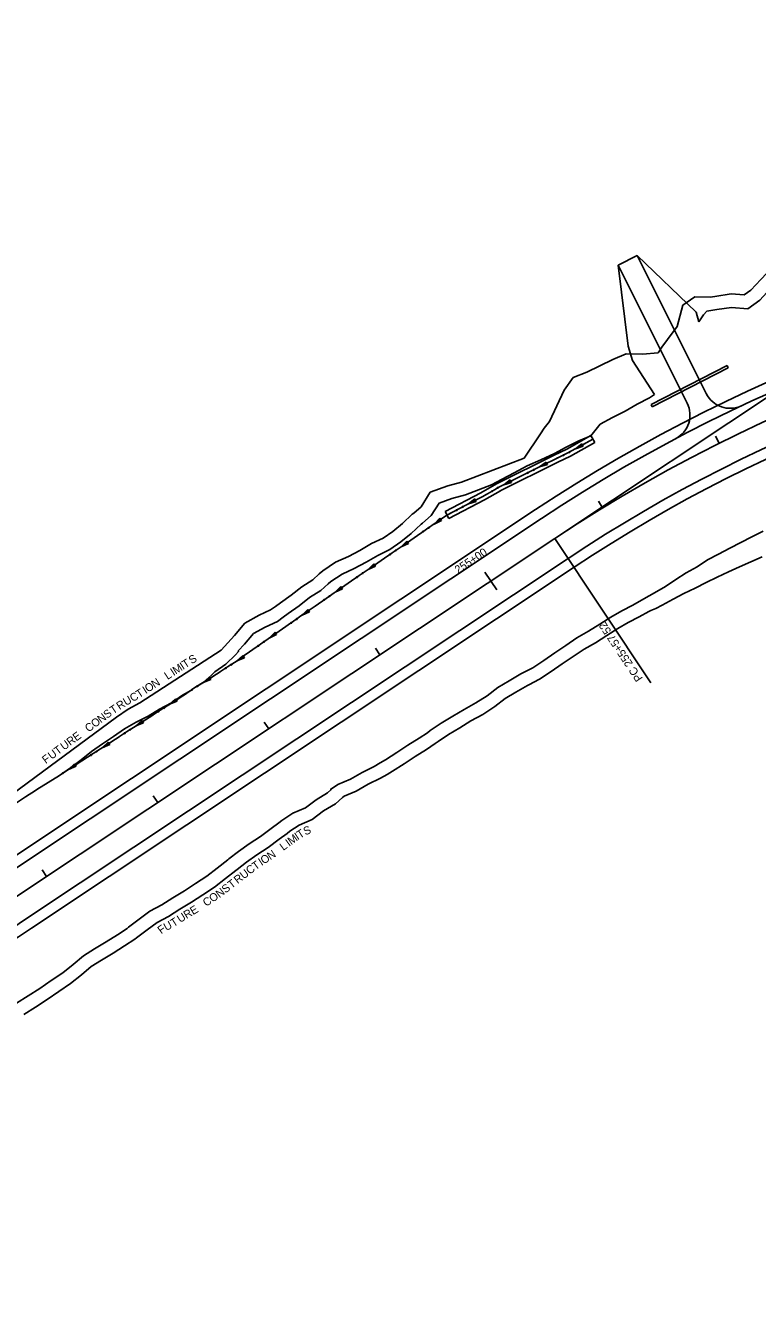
# Model space of a CAD drawing. Extents: x 979959 to 994833, y 1835619 to 1845316.
# Drawn here: x 990716 to 991264, y 1838866 to 1839827 of the extents above; entities that cross this region are included whole.
import ezdxf

# ---------------------------------------------------------------- set-up
doc = ezdxf.new("R2010")
doc.units = 0
for name, color, linetype in [('Future 5 Lane Construction Limits', 7, 'Continuous'), ('R_CONCRETE', 7, 'Continuous'), ('R_Drainage', 7, 'Continuous'), ('R_Horz Alg', 7, 'Continuous'), ('R_Horz Alg Annot', 7, 'Continuous'), ('R_Horz Alg Annot_Side Road', 7, 'Continuous'), ('R_Horz Alg Stationing', 7, 'Continuous'), ('R_Proposed Const Limits', 7, 'Continuous'), ('R_Proposed Road', 7, 'Continuous'), ('R_Special Ditch', 7, 'Continuous')]:
    doc.layers.add(name, color=color, linetype=linetype)

msp = doc.modelspace()

# ---------------------------------------------------------------- linework, layer by layer
at = {"layer": 'Future 5 Lane Construction Limits'}
for points in [[(991229, 1839623.66), (991232.48, 1839624.14), (991244.6, 1839626.05), (991254.36, 1839625.25), (991259.48, 1839628.86), (991266.81, 1839636.85), (991275.9, 1839646.46), (991287.91, 1839653.93), (991299.82, 1839656.21), (991312.97, 1839660.84), (991329.68, 1839653.8), (991340.76, 1839650.38), (991348.81, 1839650.03), (991356.19, 1839652.94), (991366.08, 1839658.22), (991377.97, 1839661.82), (991394.1, 1839664.03), (991403.52, 1839655.37)], [(991089.5, 1839502.75), (991101.68, 1839521.18), (991104.45, 1839525.27), (991108.57, 1839530.28), (991113.93, 1839542.04), (991119.42, 1839553.86), (991126.34, 1839563.44), (991136.53, 1839567.44), (991146.32, 1839572.09), (991156.04, 1839576.84), (991166.01, 1839581.11), (991178.33, 1839580.84), (991189.85, 1839581.92), (991192.79, 1839586.18), (991196.85, 1839591.87), (991204.12, 1839601.5), (991208.41, 1839617.6), (991217.51, 1839623.91), (991229, 1839623.66)], [(990862.34, 1839358.81), (990872.37, 1839370), (990880.21, 1839379.25), (990890.96, 1839385.09), (990899.52, 1839389.07), (990903.06, 1839391.67), (990906.89, 1839394.43), (990914.87, 1839400.13), (990922.99, 1839406.49), (990931.11, 1839411.62), (990935.94, 1839416.07), (990938.54, 1839418.42), (990948.16, 1839424.76), (990957.87, 1839429.23), (990966.35, 1839433.52), (990975.03, 1839438.79), (990983.86, 1839442.94), (990991.01, 1839447.99), (990998.27, 1839453.99), (991005.73, 1839460.82), (991006.85, 1839461.75), (991012.24, 1839466.48), (991019.18, 1839477.31), (991032.39, 1839482.21), (991042.56, 1839484.92), (991089.5, 1839502.75)], [(991183.02, 1839388), (991184.55, 1839388.69), (991188.27, 1839390.16), (991193.03, 1839392.59), (991201.12, 1839397.08), (991209.33, 1839401.37), (991217.71, 1839405.35), (991225.94, 1839409.57), (991234.2, 1839413.72), (991242.58, 1839417.62), (991251.02, 1839421.41), (991259.45, 1839425.17), (991267.89, 1839428.92)], [(990714.51, 1839085.77), (990723.26, 1839091.18), (990732.12, 1839096.93), (990740.78, 1839102.81), (990749.63, 1839108.85), (990757.9, 1839115.47), (990765.1, 1839121.65), (990772.88, 1839126.5), (990781.45, 1839131.66), (990790.11, 1839137.06), (990797.76, 1839142.07), (990799.03, 1839143.03), (990807.07, 1839149.05), (990814.46, 1839154.66), (990822.94, 1839159.23), (990831.56, 1839164.72), (990840.22, 1839169.9), (990848.76, 1839175.52), (990857.41, 1839181.24), (990865.66, 1839187.58), (990873.57, 1839193.74), (990874.38, 1839194.36), (990881.36, 1839199.78), (990889.18, 1839205.38), (990897.6, 1839210.93), (990905.82, 1839217.04), (990911.86, 1839221.42), (990913.83, 1839223.05), (990921.02, 1839227.72), (990930.7, 1839231.89), (990939.22, 1839238.36), (990948.19, 1839243.75), (990953.36, 1839248.47), (990954.76, 1839249.44), (990963.71, 1839253.18), (990972.73, 1839258.27), (990981.82, 1839262.81), (990986.76, 1839265.7), (990990.92, 1839268.18), (990999.6, 1839273.68), (991007.83, 1839279.21), (991016.39, 1839284.45), (991022.88, 1839288.85), (991025, 1839290.46), (991032.81, 1839295.75), (991041.21, 1839300.73), (991049.61, 1839305.84), (991058.52, 1839310.73), (991067.63, 1839316.58), (991075.34, 1839322.64), (991083.41, 1839327.32), (991092.08, 1839332.4), (991092.98, 1839332.93), (991101, 1839337.01), (991109.88, 1839342.93), (991118.14, 1839348.63), (991126.35, 1839354.18), (991134.4, 1839359.53), (991142.94, 1839364.5), (991151.61, 1839369.93), (991159.69, 1839375.14), (991167.47, 1839379.52), (991175.82, 1839383.89), (991183.02, 1839388)], [(990694.71, 1839243.01), (990783.93, 1839308.71), (990792.78, 1839314.53), (990801.53, 1839319.5), (990862.34, 1839358.81)]]:
    msp.add_lwpolyline(points, dxfattribs=at)
at = {"layer": 'R_CONCRETE'}
for p, q in [((991139.58, 1839519.81), (991142.5, 1839514.56)), ((991033.09, 1839457.55), (991030.32, 1839462.87))]:
    msp.add_line(p, q, dxfattribs=at)
for points in [[(991068.8, 1839483.64), (991112.07, 1839505.15), (991121.43, 1839509.7), (991139.58, 1839519.81)], [(991071.64, 1839478.35), (991114.71, 1839499.77), (991124.21, 1839504.38), (991142.5, 1839514.56)], [(991030.32, 1839462.87), (991057.01, 1839476.8), (991068.8, 1839483.64)], [(991033.09, 1839457.55), (991059.9, 1839471.54), (991071.81, 1839478.45)]]:
    msp.add_lwpolyline(points, dxfattribs=at)
at = {"layer": 'R_Drainage'}
for p, q in [((991241.59, 1839572.36), (991184.62, 1839543.21)), ((991242.5, 1839570.58), (991185.53, 1839541.43)), ((991241.59, 1839572.36), (991242.5, 1839570.58)), ((991184.62, 1839543.21), (991185.53, 1839541.43))]:
    msp.add_line(p, q, dxfattribs=at)
at = {"layer": 'R_Horz Alg'}
msp.add_line((991112.49, 1839442.65), (990705.95, 1839172.04), dxfattribs=at)
msp.add_arc((991747.45, 1838488.74), 1145.92, 61.24197, 123.64915, dxfattribs=at)
at = {"layer": 'R_Horz Alg Annot'}
msp.add_lwpolyline([(991112.49, 1839442.65), (991184.53, 1839334.43)], dxfattribs=at)
at = {"layer": 'R_Horz Alg Annot_Side Road'}
msp.add_line((991112.49, 1839442.65), (991690.28, 1839827.25), dxfattribs=at)
at = {"layer": 'R_Horz Alg Stationing'}
for points in [[(991233.02, 1839519.4), (991235.7, 1839514.03)], [(991145.15, 1839470.64), (991148.28, 1839465.53)], [(991060.18, 1839417.44), (991069.04, 1839404.12)], [(990978.04, 1839360.36), (990981.37, 1839355.37)], [(990894.8, 1839304.95), (990898.12, 1839299.96)], [(990811.55, 1839249.54), (990814.88, 1839244.55)], [(990728.31, 1839194.13), (990731.63, 1839189.14)]]:
    msp.add_lwpolyline(points, dxfattribs=at)
at = {"layer": 'R_Proposed Const Limits'}
for p, q in [((991120.91, 1839511.12), (991130.47, 1839515.91)), ((991102.07, 1839501.66), (991091.84, 1839497.03)), ((991055.22, 1839479.03), (991065.08, 1839482.76)), ((990850.42, 1839335.52), (990841.88, 1839330.32)), ((990749.47, 1839270.62), (990741.2, 1839265))]:
    msp.add_line(p, q, dxfattribs=at)
for points in [[(991160.04, 1839647.71), (991167.45, 1839586.9), (991170.67, 1839576.16), (991187.29, 1839550.51)], [(991174.35, 1839654.85), (991218.49, 1839612.37), (991220.39, 1839605.2)], [(991220.39, 1839605.2), (991223.85, 1839610.32), (991226.48, 1839613.23), (991233.93, 1839614.25), (991244.98, 1839615.99), (991257.16, 1839614.98), (991266.12, 1839621.31), (991274.12, 1839630.04), (991282.27, 1839638.65), (991291.62, 1839644.46), (991302.44, 1839646.53), (991312.65, 1839650.13), (991326.25, 1839644.39), (991339.04, 1839640.44), (991350.5, 1839639.94), (991360.4, 1839643.85), (991369.92, 1839648.94), (991380.11, 1839652.02), (991390.79, 1839653.49), (991406.04, 1839639.48)], [(991130.47, 1839515.91), (991139.57, 1839519.69), (991146.56, 1839528.47), (991155.81, 1839533.4), (991165.13, 1839538.2), (991174.27, 1839543.31), (991183.57, 1839548.13), (991187.29, 1839550.51)], [(991102.07, 1839501.66), (991112.33, 1839506.49), (991120.91, 1839511.12)], [(991065.08, 1839482.76), (991073.02, 1839487.23), (991082.12, 1839491.79), (991091.84, 1839497.03)], [(990850.42, 1839335.52), (990857.69, 1839342.65), (990865.88, 1839348.4), (990873.17, 1839355.49), (990875.56, 1839357.94), (990875.32, 1839358.31), (990879.9, 1839363.42), (990886.63, 1839371.36), (990895.45, 1839376.16), (990904.63, 1839380.42), (990908.94, 1839383.58), (990912.72, 1839386.3), (990920.86, 1839392.12), (990928.76, 1839398.3), (990937.22, 1839403.65), (990942.68, 1839408.68), (990944.68, 1839410.49), (990953.03, 1839415.99), (990962.22, 1839420.23), (990971.21, 1839424.77), (990979.76, 1839429.97), (990988.91, 1839434.27), (990997.09, 1839440.04), (991004.83, 1839446.44), (991012.3, 1839453.28), (991013.34, 1839454.14), (991019.9, 1839459.9), (991025.79, 1839469.1), (991035.43, 1839472.67), (991045.63, 1839475.39), (991055.22, 1839479.03)], [(990709.1, 1839094.18), (990717.91, 1839099.63), (990726.59, 1839105.26), (990735.16, 1839111.08), (990743.68, 1839116.9), (990751.52, 1839123.17), (990759.17, 1839129.73), (990767.65, 1839135.02), (990776.23, 1839140.19), (990784.72, 1839145.48), (990792.01, 1839150.26), (990793.04, 1839151.03), (990801.05, 1839157.03), (990809.04, 1839163.09), (990817.87, 1839167.86), (990826.31, 1839173.23), (990834.9, 1839178.37), (990843.25, 1839183.87), (990851.6, 1839189.38), (990859.55, 1839195.49), (990867.46, 1839201.65), (990868.28, 1839202.28), (990875.38, 1839207.79), (990883.52, 1839213.62), (990891.87, 1839219.12), (990899.9, 1839225.1), (990905.72, 1839229.33), (990907.9, 1839231.13), (990916.29, 1839236.57), (990925.63, 1839240.59), (990933.61, 1839246.65), (990942.19, 1839251.81), (990944.68, 1839254.09), (990944.46, 1839254.44), (990949.91, 1839258.25), (990959.31, 1839262.18), (990968.04, 1839267.11), (990977.06, 1839271.61), (990981.67, 1839274.31), (990985.68, 1839276.7), (990994.13, 1839282.06), (991002.43, 1839287.63), (991010.97, 1839292.85), (991017.04, 1839296.97), (991019.16, 1839298.59), (991027.45, 1839304.19), (991036.05, 1839309.31), (991044.61, 1839314.5), (991053.4, 1839319.33), (991061.82, 1839324.73), (991069.71, 1839330.94), (991078.38, 1839335.96), (991087.02, 1839341.03), (991088.17, 1839341.71), (991095.95, 1839345.66), (991104.27, 1839351.21), (991112.5, 1839356.88), (991120.78, 1839362.49), (991129.11, 1839368.02), (991137.77, 1839373.06), (991146.25, 1839378.37), (991154.52, 1839383.71), (991162.7, 1839388.31), (991171.03, 1839392.67), (991179.16, 1839397.31), (991187.25, 1839402), (991195.38, 1839406.64), (991203.2, 1839411.76), (991211.04, 1839416.9), (991219.18, 1839421.5), (991227.07, 1839426.57), (991235.31, 1839430.99), (991243.61, 1839435.32), (991251.96, 1839439.54), (991260.23, 1839443.92), (991268.55, 1839448.21)], [(990749.47, 1839270.62), (990757.55, 1839276.53), (990765.34, 1839282.87), (990773.53, 1839288.61), (990781.79, 1839294.25), (990790.11, 1839299.81), (990798.75, 1839304.87), (990799.67, 1839305.35), (990807.72, 1839309.44), (990816.31, 1839314.59), (990825.11, 1839319.41), (990833.38, 1839325.04), (990839.67, 1839328.57)], [(990839.69, 1839328.54), (990841.88, 1839330.32)], [(990541.64, 1839140.81), (990550.41, 1839144.98), (990565.69, 1839158.08), (990584.19, 1839164.05), (990592.48, 1839169.08), (990600.74, 1839174.17), (990608.96, 1839179.31), (990617.31, 1839184.24), (990625.76, 1839189.01), (990634.19, 1839193.82), (990642.59, 1839198.68), (990650.8, 1839203.86), (990658.77, 1839209.4), (990666.82, 1839214.81), (990674.9, 1839220.22), (990683.25, 1839225.73), (990691.16, 1839231.9), (990699.42, 1839237.53), (990707.56, 1839243.35), (990715.85, 1839248.95), (990723.21, 1839253.62), (990724.3, 1839254.3), (990732.75, 1839259.64), (990741.2, 1839265)]]:
    msp.add_lwpolyline(points, dxfattribs=at)
at = {"layer": 'R_Proposed Road'}
for p, q in [((991160.04, 1839647.71), (991174.35, 1839654.85)), ((991098.09, 1839464.29), (990691.55, 1839193.69)), ((991102.52, 1839457.64), (990695.98, 1839187.03)), ((991122.47, 1839427.67), (990715.93, 1839157.06)), ((991126.9, 1839421.01), (990720.36, 1839150.4))]:
    msp.add_line(p, q, dxfattribs=at)
for points in [[(991160.04, 1839647.71), (991211.72, 1839544.16)], [(991174.35, 1839654.85), (991226.03, 1839551.31)]]:
    msp.add_lwpolyline(points, dxfattribs=at)
for centre, radius, start, end in [((991747.45, 1838488.74), 1171.92, 67.29702, 123.64915), ((991747.45, 1838488.74), 1163.92, 67.29702, 123.64915), ((991747.45, 1838488.74), 1127.92, 70.20618, 123.64915), ((991747.45, 1838488.74), 1119.92, 70.20618, 123.64915), ((991243.93, 1839560.24), 20, 206.52507, 295.16988), ((991193.82, 1839535.23), 20, 297.88026, 26.52507), ((989647.69, 1840761.9), 1927.86, 281.66438, 303.64915), ((989647.69, 1840761.9), 1935.86, 281.66438, 303.64915)]:
    msp.add_arc(centre, radius, start, end, dxfattribs=at)
at = {"layer": 'R_Special Ditch'}
for p, q in [((991132.66, 1839513.73), (991127.94, 1839509.89)), ((991127.94, 1839509.89), (991133.69, 1839511.88)), ((991133.69, 1839511.88), (991132.66, 1839513.73)), ((991106.03, 1839499.98), (991101.12, 1839496.36)), ((991101.12, 1839496.36), (991106.97, 1839498.09)), ((991106.97, 1839498.09), (991106.03, 1839499.98)), ((991079.13, 1839486.61), (991074.23, 1839482.99)), ((991074.23, 1839482.99), (991080.07, 1839484.71)), ((991080.07, 1839484.71), (991079.13, 1839486.61)), ((991070.14, 1839480.95), (991067.24, 1839479.02)), ((991070.14, 1839480.95), (991070.14, 1839480.95)), ((991052.69, 1839472.35), (991047.86, 1839468.64)), ((991047.86, 1839468.64), (991053.67, 1839470.48)), ((991053.67, 1839470.48), (991052.69, 1839472.35)), ((991026.32, 1839457.78), (991021.98, 1839453.5)), ((991021.98, 1839453.5), (991027.52, 1839456.04)), ((991027.52, 1839456.04), (991026.32, 1839457.78)), ((991001.59, 1839440.73), (990997.25, 1839436.45)), ((990997.25, 1839436.45), (991002.79, 1839438.99)), ((991002.79, 1839438.99), (991001.59, 1839440.73)), ((990976.86, 1839423.68), (990972.52, 1839419.4)), ((990972.52, 1839419.4), (990978.06, 1839421.93)), ((990978.06, 1839421.93), (990976.86, 1839423.68)), ((990952.13, 1839406.62), (990947.79, 1839402.35)), ((990953.33, 1839404.88), (990952.13, 1839406.62)), ((990947.79, 1839402.35), (990953.33, 1839404.88)), ((990927.47, 1839389.46), (990923.16, 1839385.16)), ((990923.16, 1839385.16), (990928.69, 1839387.72)), ((990928.69, 1839387.72), (990927.47, 1839389.46)), ((990902.84, 1839372.26), (990898.53, 1839367.96)), ((990898.53, 1839367.96), (990904.05, 1839370.53)), ((990904.05, 1839370.53), (990902.84, 1839372.26)), ((990878.75, 1839354.96), (990874.28, 1839350.82)), ((990874.28, 1839350.82), (990879.9, 1839353.18)), ((990879.9, 1839353.18), (990878.75, 1839354.96)), ((990853.5, 1839338.69), (990849.03, 1839334.56)), ((990854.65, 1839336.92), (990853.5, 1839338.69)), ((990849.03, 1839334.56), (990854.65, 1839336.92)), ((990828.27, 1839322.44), (990823.8, 1839318.3)), ((990823.8, 1839318.3), (990829.41, 1839320.66)), ((990829.41, 1839320.66), (990828.27, 1839322.44)), ((990803.02, 1839306.17), (990798.54, 1839302.03)), ((990798.54, 1839302.03), (990804.16, 1839304.39)), ((990804.16, 1839304.39), (990803.02, 1839306.17)), ((990777.78, 1839289.87), (990773.32, 1839285.73)), ((990778.93, 1839288.1), (990777.78, 1839289.87)), ((990773.32, 1839285.73), (990778.93, 1839288.1)), ((990752.55, 1839273.57), (990748.09, 1839269.43)), ((990748.09, 1839269.43), (990753.7, 1839271.8)), ((990753.7, 1839271.8), (990752.55, 1839273.57)), ((990749.61, 1839270.41), (990741.2, 1839265))]:
    msp.add_line(p, q, dxfattribs=at)
for points in [[(991141.04, 1839517.19), (991122.82, 1839507.04), (991113.39, 1839502.46), (991103.99, 1839497.79)], [(991141.04, 1839517.19), (991127.94, 1839509.89)], [(991114.56, 1839503.03), (991113.39, 1839502.46), (991103.99, 1839497.79), (991101.12, 1839496.36)], [(991114.6, 1839503.04), (991114.56, 1839503.03)], [(991103.99, 1839497.79), (991070.14, 1839480.95)], [(991087.66, 1839489.67), (991074.23, 1839482.99)], [(991087.69, 1839489.68), (991087.66, 1839489.67)], [(991067.24, 1839479.02), (991058.46, 1839474.17), (991049.54, 1839469.52), (991040.62, 1839464.86), (991031.71, 1839460.21), (991023.47, 1839454.54), (991016.34, 1839449.62), (991015.24, 1839448.86), (991007.01, 1839443.18), (990998.77, 1839437.5), (990990.54, 1839431.82), (990982.31, 1839426.15), (990974.07, 1839420.47), (990965.84, 1839414.79), (990957.61, 1839409.11), (990949.37, 1839403.43), (990947.18, 1839401.92), (990941.16, 1839397.72), (990932.96, 1839392), (990924.76, 1839386.27), (990916.56, 1839380.55), (990912.74, 1839377.88), (990908.36, 1839374.82), (990900.15, 1839369.1), (990891.95, 1839363.37), (990883.75, 1839357.64), (990878.3, 1839353.84), (990878.49, 1839353.53), (990875.68, 1839351.72), (990867.27, 1839346.31), (990858.86, 1839340.89), (990850.46, 1839335.47), (990841.88, 1839330.32)], [(991061.13, 1839475.64), (991058.46, 1839474.17), (991049.54, 1839469.52), (991047.86, 1839468.64)], [(991061.16, 1839475.66), (991061.13, 1839475.64)], [(991034.53, 1839461.68), (991031.71, 1839460.21), (991023.47, 1839454.54), (991021.98, 1839453.5)], [(991034.56, 1839461.7), (991034.53, 1839461.68)], [(991009.6, 1839444.97), (991007.01, 1839443.18), (990998.77, 1839437.5), (990997.25, 1839436.45)], [(991009.63, 1839444.99), (991009.6, 1839444.97)], [(990984.87, 1839427.91), (990982.31, 1839426.15), (990974.07, 1839420.47), (990972.52, 1839419.4)], [(990984.9, 1839427.94), (990984.87, 1839427.91)], [(990960.14, 1839410.86), (990957.61, 1839409.11), (990949.37, 1839403.43), (990947.79, 1839402.35)], [(990960.17, 1839410.88), (990960.14, 1839410.86)], [(990935.46, 1839393.74), (990932.96, 1839392), (990924.76, 1839386.27), (990923.16, 1839385.16)], [(990935.49, 1839393.76), (990935.46, 1839393.74)], [(990910.83, 1839376.55), (990908.36, 1839374.82), (990900.15, 1839369.1), (990898.53, 1839367.96)], [(990910.86, 1839376.57), (990910.83, 1839376.55)], [(990886.2, 1839359.35), (990883.75, 1839357.64), (990878.3, 1839353.84), (990878.49, 1839353.53), (990875.68, 1839351.72), (990874.28, 1839350.82)], [(990886.23, 1839359.38), (990886.2, 1839359.35)], [(990861.64, 1839342.68), (990858.86, 1839340.89), (990850.46, 1839335.47), (990849, 1839334.6)], [(990861.67, 1839342.7), (990861.64, 1839342.68)], [(990841.88, 1839330.32), (990839.69, 1839328.54), (990833.64, 1839324.64), (990827.22, 1839320.5), (990825.23, 1839319.23), (990816.83, 1839313.81), (990808.42, 1839308.39), (990800.88, 1839303.53), (990800.01, 1839302.98), (990791.61, 1839297.55), (990783.21, 1839292.12), (990774.81, 1839286.69), (990766.41, 1839281.27), (990758.01, 1839275.84), (990749.61, 1839270.41)], [(990836.41, 1839326.42), (990833.64, 1839324.64), (990827.22, 1839320.5), (990825.23, 1839319.23), (990823.8, 1839318.3)], [(990836.44, 1839326.44), (990836.41, 1839326.42)], [(990811.15, 1839310.16), (990808.42, 1839308.39), (990800.88, 1839303.53), (990800.01, 1839302.98), (990798.55, 1839302.03)], [(990811.19, 1839310.18), (990811.16, 1839310.16)], [(990785.92, 1839293.87), (990783.21, 1839292.12), (990774.81, 1839286.69), (990773.32, 1839285.73)], [(990785.95, 1839293.89), (990785.92, 1839293.87)], [(990760.68, 1839277.57), (990758.01, 1839275.84), (990749.61, 1839270.41), (990748.08, 1839269.43)], [(990760.72, 1839277.59), (990760.69, 1839277.57)]]:
    msp.add_lwpolyline(points, dxfattribs=at)
for centre in [(991119.09, 1839505.19), (991123.58, 1839507.42), (991092.17, 1839491.87), (991096.66, 1839494.1), (991065.54, 1839478.04), (991069.79, 1839480.68), (991039, 1839463.98), (991043.44, 1839466.29), (991013.75, 1839447.79), (991017.88, 1839450.63), (990993.15, 1839433.58), (990989.02, 1839430.73), (990968.42, 1839416.53), (990964.3, 1839413.68), (990939.6, 1839396.59), (990943.71, 1839399.45), (990914.97, 1839379.39), (990919.08, 1839382.26), (990890.34, 1839362.2), (990894.45, 1839365.07), (990870.09, 1839348.08), (990865.88, 1839345.37), (990840.58, 1839329.22), (990844.73, 1839331.99), (990815.4, 1839312.85), (990819.61, 1839315.56), (990794.36, 1839299.28), (990790.15, 1839296.56), (990764.92, 1839280.26), (990769.13, 1839282.98), (990743.9, 1839266.69)]:
    msp.add_circle(centre, 0.375, dxfattribs=at)

# ---------------------------------------------------------------- texts
at = {"layer": 'Future 5 Lane Construction Limits'}
for s, rotation, p in [('M', 32.88029, (990828.47, 1839340.49)), ('I', 32.88029, (990833.86, 1839343.97)), ('T', 32.88029, (990835.53, 1839345.05)), ('S', 32.88029, (990840.45, 1839348.23)), ('N', 32.88029, (990812.48, 1839330.15)), ('L', 32.88029, (990822.28, 1839336.48)), ('I', 32.88029, (990826.8, 1839339.41)), ('T', 32.88029, (990800.97, 1839322.71)), ('I', 32.88029, (990805.89, 1839325.89)), ('O', 32.88029, (990807.56, 1839326.97)), ('R', 33.28443, (990786.33, 1839313.88)), ('U', 29.63315, (990791.07, 1839317)), ('C', 29.63315, (990796.08, 1839319.85)), ('N', 36.36873, (990772.33, 1839303.9)), ('S', 36.36873, (990776.9, 1839307.26)), ('T', 33.28443, (990781.44, 1839310.67)), ('C', 36.36873, (990763.05, 1839297.06)), ('O', 36.36873, (990767.62, 1839300.43)), ('U', 36.36873, (990744.68, 1839283.53)), ('R', 36.36873, (990749.32, 1839286.95)), ('E', 36.36873, (990753.88, 1839290.31)), ('F', 36.36873, (990730.98, 1839273.45)), ('U', 36.36873, (990735.32, 1839276.64)), ('T', 36.36873, (990739.96, 1839280.06)), ('T', 32.94602, (990921.49, 1839217.33)), ('S', 23.32642, (990925.58, 1839219.92)), ('L', 35.98491, (990908.98, 1839208.26)), ('I', 35.98491, (990913.34, 1839211.42)), ('M', 35.98491, (990914.95, 1839212.59)), ('I', 32.94602, (990919.82, 1839216.26)), ('O', 33.37727, (990894.39, 1839198.08)), ('N', 33.37727, (990899.28, 1839201.3)), ('U', 37.80935, (990879.31, 1839186.84)), ('C', 37.80935, (990883.86, 1839190.37)), ('T', 35.62502, (990888.2, 1839193.65)), ('I', 33.37727, (990892.73, 1839196.98)), ('T', 37.9108, (990870.22, 1839179.77)), ('R', 37.9108, (990874.84, 1839183.36)), ('O', 33.45582, (990855.87, 1839169.48)), ('N', 37.53701, (990861.19, 1839172.84)), ('S', 37.53701, (990865.69, 1839176.29)), ('E', 30.87034, (990841.31, 1839160.1)), ('C', 33.36768, (990851.13, 1839166.35)), ('U', 28.34893, (990821.29, 1839148.16)), ('T', 32.49725, (990826.78, 1839151.05)), ('U', 32.49725, (990831.72, 1839154.19)), ('R', 30.87034, (990836.44, 1839157.19)), ('F', 37.20105, (990817.56, 1839145.75))]:
    msp.add_text(s, height=6, rotation=rotation, dxfattribs=at).set_placement(p)
at = {"layer": 'R_Horz Alg Annot'}
msp.add_text('PC 255+57.52', height=6, rotation=123.64915, dxfattribs=at).set_placement((991178.7, 1839337.77))
at = {"layer": 'R_Horz Alg Stationing'}
msp.add_text('255+00', height=6, rotation=33.64915, dxfattribs=at).set_placement((991039.95, 1839415.99))

doc.saveas('drawing.dxf')
